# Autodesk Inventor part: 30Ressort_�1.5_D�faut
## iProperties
Created: 2011-01
Part Number: 30Ressort_�1.5_D�faut
Document SubType Name: Modeling
Designer: eric
Density: 1 g/cm^3
Mass: 0.414767 g
Surface Area: 11.9115 cm^2
Volume: 0.414767 cm^3
Author: eric
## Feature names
1. Base1
